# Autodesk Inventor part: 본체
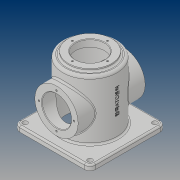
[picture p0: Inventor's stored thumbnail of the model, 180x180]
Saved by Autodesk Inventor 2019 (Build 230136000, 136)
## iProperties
Created: 2019-03
Part Number: 본체
Material: 일반
Document SubType Name: Modeling
Designer: PC312-02
Density: 1 g/cm^3
Appearance: 기본값
Author: PC312-02
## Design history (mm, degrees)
sketch "스케치1"
  geometry: C1 r 50 at (0, 0); 1 further point
  constraints: 1 centre point, 1 coincident
  dimensions: "d0" = 100 diameter of C1
extrude "돌출1" new body sketch "스케치1" distance "d1" = 120; taper "d2" = 0 deg
sketch "스케치2"
  geometry: C1 r 45 at (0, 0); 1 further point
  constraints: 1 centre point, 1 coincident
  dimensions: "d3" = 90 diameter of C1
extrude "돌출2" cut sketch "스케치2" distance "d4" = 112; taper "d5" = 0 deg
sketch "스케치3"
  geometry: L1 (70, 70)-(-70, 70); L2 (-70, 70)-(-70, -70); L3 (-70, -70)-(70, -70); L4 (70, -70)-(70, 70); L5 (70, 70)-(-70, -70); L6 (-70, 70)-(70, -70); C1 r 45 at (0, 0) reference; 1 further point
  constraints: 12 end point, 2 midpoint, 2 parallel, 1 horizontal, 1 perpendicular
  dimensions: "d6" = 140 distance of L3.end L2.end; "d7" = 140 distance of L2.end L1.end
extrude "돌출3" join sketch "스케치3" distance "d8" = 10; taper "d9" = 0 deg
node "작업 평면1"
sketch "스케치4"
  geometry: L1 (70, 0)-(-70, 0) reference; C1 r 40 at (0, 60); 2 further points
  constraints: 1 centre point, 1 midpoint, 1 vertical alignment
  dimensions: "d11" = 60 distance from line of L1 C1.centre; "d12" = 80 diameter of C1
extrude "돌출4" join sketch "스케치4" stored distance "d13" = 10; taper "d14" = 0 deg
sketch "스케치5"
  geometry: C1 r 40 at (0, 0); 1 further point
  constraints: 1 centre point, 1 coincident
  dimensions: "d15" = 80 diameter of C1
extrude "돌출5" join sketch "스케치5" distance "d16" = 5; taper "d17" = 0 deg
sketch "스케치6"
  geometry: C1 r 40 at (0, 0) reference; 2 further points
  constraints: 1 vertical alignment
  dimensions: "d18" = 32.5 distance of C1.centre point (0, 32.5)
hole "구멍1" sketch "스케치6" at (0, 32.5) diameter "d19" = 3.242; stored, may be unused: countersink angle "d23" = 90 deg, drill point angle "d25" = 118 deg; dims "d20" = 8, "d21" = 4, "d22" = 2, "d24" = 10
sketch "스케치7"
  geometry: 2 further points
  constraints: 1 vertical alignment
  dimensions: "d29" = 32.5 distance of point (0, 0) point (0, 32.5)
hole "구멍2" sketch "스케치7" at (0, 32.5) diameter "d30" = 3.242; stored, may be unused: countersink angle "d34" = 90 deg, drill point angle "d36" = 118 deg; dims "d31" = 8, "d32" = 4, "d33" = 2, "d35" = 10
sketch "스케치8"
  geometry: C1 r 40 at (0, 0) reference; C2 r 27 at (0, 0); 1 further point
  constraints: 1 centre point, 1 coincident
  dimensions: "d40" = 54 diameter of C2
extrude "돌출6" cut sketch "스케치8" extent not by distance; stored distance "d41" = 5; taper "d42" = 0 deg
sketch "스케치9"
  geometry: C1 r 27 at (0, 0); 1 further point
  constraints: 1 centre point, 1 coincident
  dimensions: "d43" = 54 diameter of C1
extrude "돌출7" cut sketch "스케치9" extent not by distance; stored distance "d44" = 5; taper "d45" = 0 deg
fillet "모깎기1" dims "d46" = 10
sketch "스케치10"
  geometry: A1 r 10 centre (-60, -60) between (-70, -60) and (-60, -70) reference; A2 r 10 centre (60, -60) between (60, -70) and (70, -60) reference; A3 r 10 centre (60, 60) between (70, 60) and (60, 70) reference; A4 r 10 centre (-60, 60) between (-60, 70) and (-70, 60) reference; 5 further points
  constraints: 4 coincident
hole "구멍3" sketch "스케치10" at (-60, -60), (60, -60), (60, 60), (-60, 60) diameter "d47" = 9; stored, may be unused: countersink angle "d51" = 90 deg, drill point angle "d53" = 118 deg; dims "d48" = 8, "d49" = 4, "d50" = 2, "d52" = 10
fillet "모깎기2" dims "d54" = 3
fillet "모깎기3" dims "d55" = 3
chamfer "모따기1" distance "d56" = 1; stored, may be unused: second distance "d57" = 2, angle "d58" = 45 deg
node "작업 평면2"
sketch "스케치11"
  geometry: L1 (0, -60)-(0, 60) reference; 3 further points
  constraints: 1 horizontal alignment, 1 midpoint, 1 other
  dimensions: "d60" = 70 distance from line of L1 point (70, 0)
feature "엠보싱1" sketch "스케치11" dims "d61" = 0.5, "d62" = 0
fillet "모깎기4" dims "d63" = 5
node "솔리드1"
pattern_circular "원형 패턴1" dims angle "d27" = 360 deg
mirror "미러1"
pattern_circular "원형 패턴2" dims angle "d38" = 360 deg
other parameters: "d10" = 62
